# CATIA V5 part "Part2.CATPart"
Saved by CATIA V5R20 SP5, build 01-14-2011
Part number: Part2
Bounding box of the stored display mesh (mm): x -24.106 to 24.106, y -23.93 to 24.042, z 0 to 80
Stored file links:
  C:\!Work\00_Catia\Makro+Unfold\sestava\Nová složka\Part2.CATPart
  C:\!Work\00_Catia\Makro+Unfold\sestava\Nová složka\Part1.CATPart
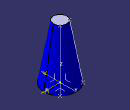
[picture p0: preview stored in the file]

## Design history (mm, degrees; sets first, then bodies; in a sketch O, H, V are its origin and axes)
AxisSystem1: origin (0, 0, 0), X (1, 0, 0), Y (0, 1, 0), Z (0, 0, 1)
Set1
  Plane1: type Offset, RefPlane XY plane of AxisSystem1, Offset 80
  Line1: type PtPt, FirstPoint Sketch1.P3, SecondPoint Sketch2.P3
  Line2: type PtPt, FirstPoint Sketch1.P1, SecondPoint Sketch2.P1
  Sketch1 on start face of Pad1, origin (0, 0, 0), H (1, 0, 0), V (0, -1, 0)
    reference projected circle E1 centre (0, 0) radius 24.1062 from edge [face of Pad1 from Sketch3.A1 | start face of Pad1]
    point P1 (17.0456, -17.0456)
    construction line L1 (17.0456, -17.0456) -> (0, 0)
    point P2 (0, 0)
    construction line L2 (0, 0) -> (-17.0456, -17.0456)
    point P3 (-17.0456, -17.0456)
    coincidence: P1 E1, P3 E1
    concentricity: P2 E1
    perpendicularity: L1 L2
    symmetry: L2 L1 V
  Sketch2 on Plane1, origin (0, 0, 80), H (1, 0, 0), V (0, -1, 0)
    reference projected circle E1 centre (0, 0) radius 10 from end face of Pad1
    point P1 (7.0711, -7.0711)
    construction line L1 (7.0711, -7.0711) -> (0, 0)
    point P2 (0, 0)
    construction line L2 (0, 0) -> (-7.0711, -7.0711)
    point P3 (-7.0711, -7.0711)
    angle L1 L2 = 90 (reference)
    coincidence: P1 E1, P3 E1
    concentricity: P2 E1
    perpendicularity: L1 L2
    symmetry: L2 L1 V
Body1 (main body)
  Sketch3 on xy-plane, origin (0, 0, 0), H (1, 0, 0), V (0, 1, 0)
    circle A1 centre (0, 0) radius 10
    reference projected point E1 (0, 0) from vertex [YZ plane of AxisSystem1 | ZX plane of AxisSystem1 | XY plane of AxisSystem1]
    radius A1 = 10
    concentricity: E1 A1
  Pad1: profile Sketch3, direction (0, 0, 1), length 80
  Draft1: Angle 10, Neutral end face of Pad1, PullDir end face of Pad1, SupportToDraft face of Pad1 from Sketch3.A1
